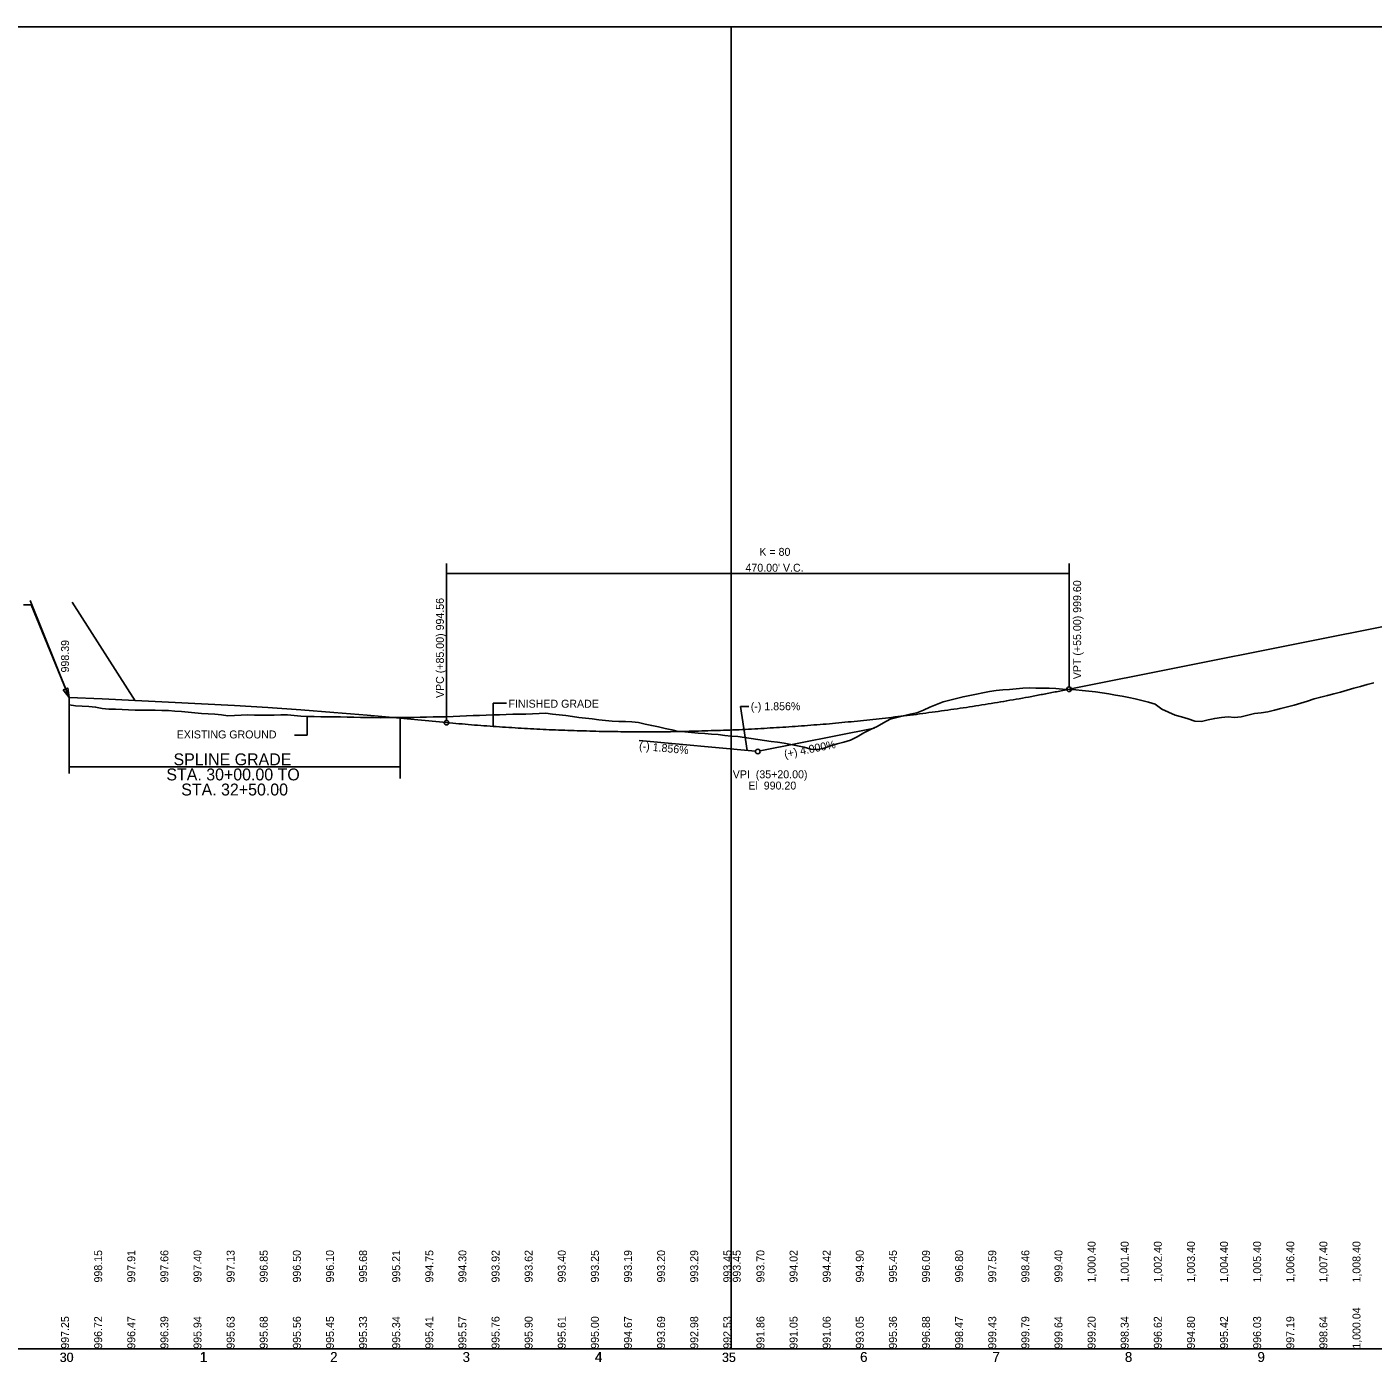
# Model space of a CAD drawing. Extents: x 1150 to 16975538, y 12057 to 12564120.
# Drawn here: x 16973506 to 16974522, y 12563110 to 12564118 of the extents above; entities that cross this region are included whole.
import ezdxf

# ---------------------------------------------------------------- set-up
doc = ezdxf.new("R2010")
doc.units = 0
for name, color, linetype in [('ANNOT_CONTOUR', 7, 'Continuous'), ('CLS_P_Shld_Gore', 7, 'Continuous'), ('Default', 7, 'Continuous'), ('RD_DDB_Profile_EX', 7, 'Continuous'), ('RD_DDB_StaTX', 7, 'Continuous'), ('RD_DDB_StripGrade', 7, 'Continuous'), ('RD_EX_Conc-ZZ', 7, 'Continuous'), ('RD_GPK_Profile_Cell', 7, 'Continuous'), ('RD_HC_CL_50', 7, 'Continuous'), ('RD_HC_TX_Sta20', 7, 'Continuous'), ('RD_PD_SuperShp1', 7, 'Continuous'), ('RD_Sketch1', 7, 'Continuous'), ('RD_Sketch7', 7, 'Continuous'), ('RD_TX_Utilities', 7, 'Continuous'), ('RD_XS_Misc_Line', 7, 'Continuous')]:
    doc.layers.add(name, color=color, linetype=linetype)

msp = doc.modelspace()

# ---------------------------------------------------------------- linework, layer by layer
at = {"layer": 'CLS_P_Shld_Gore'}
for p, q in [((16973868.1, 12563607.3), (16973858.1, 12563607.3)), ((16973858.1, 12563607.3), (16973858.1, 12563589.8))]:
    msp.add_line(p, q, dxfattribs=at)
at = {"layer": 'Default'}
for points in [[(16972537.8, 12563119.9), (16974037.8, 12563119.9), (16974037.8, 12564118.1), (16972537.8, 12564118.1)], [(16974037.8, 12563119.9), (16975537.8, 12563119.9), (16975537.8, 12564118.1), (16974037.8, 12564118.1)]]:
    msp.add_lwpolyline(points, close=True, dxfattribs=at)
at = {"layer": 'RD_DDB_Profile_EX'}
for points in [[(16974037.8, 12563582.6), (16974042.8, 12563582.2), (16974047.8, 12563581.6), (16974052.8, 12563580.7), (16974057.8, 12563579.9), (16974062.8, 12563579.2), (16974067.8, 12563578.5), (16974072.8, 12563577.9), (16974077.8, 12563577.2), (16974082.8, 12563576.2), (16974087.8, 12563575.2), (16974092.8, 12563574.1), (16974097.8, 12563572.8), (16974102.8, 12563572.4), (16974107.8, 12563573.4), (16974112.8, 12563575.2), (16974117.8, 12563576.6), (16974122.8, 12563577.9), (16974127.8, 12563579.5), (16974132.8, 12563581.9), (16974137.8, 12563585.1), (16974142.8, 12563587.5), (16974147.8, 12563589.9), (16974152.8, 12563592.6), (16974157.8, 12563595.3), (16974162.8, 12563596.7), (16974167.8, 12563597.9), (16974172.8, 12563599), (16974177.8, 12563600.1), (16974182.8, 12563602.1), (16974187.8, 12563604.3), (16974192.8, 12563606.5), (16974197.8, 12563608.4), (16974202.8, 12563609.7), (16974207.8, 12563611), (16974212.8, 12563612.3), (16974217.8, 12563613.1), (16974222.8, 12563614.1), (16974227.8, 12563615.2), (16974232.8, 12563616.3), (16974237.8, 12563617.1), (16974242.8, 12563617.5), (16974247.8, 12563617.8), (16974252.8, 12563618.2), (16974257.8, 12563618.7), (16974262.8, 12563618.9), (16974267.8, 12563618.8), (16974272.8, 12563618.7), (16974277.8, 12563618.8), (16974282.8, 12563618.5), (16974287.8, 12563618.1), (16974292.8, 12563617.7), (16974297.8, 12563617.4), (16974302.8, 12563617), (16974307.8, 12563616.6), (16974312.8, 12563615.9), (16974317.8, 12563615.2), (16974322.8, 12563614.4), (16974327.8, 12563613.5), (16974332.8, 12563612.6), (16974337.8, 12563611.6), (16974342.8, 12563610.6), (16974347.8, 12563609.4), (16974352.8, 12563608.1), (16974357.8, 12563606.7), (16974362.8, 12563603), (16974367.8, 12563600.6), (16974372.8, 12563598.4), (16974377.8, 12563597), (16974382.8, 12563595.5), (16974387.8, 12563593.9), (16974392.8, 12563593.6), (16974397.8, 12563594.8), (16974402.8, 12563595.9), (16974407.8, 12563596.7), (16974412.8, 12563597), (16974417.8, 12563596.7), (16974422.8, 12563597.2), (16974427.8, 12563598.4), (16974432.8, 12563599.5), (16974437.8, 12563600), (16974442.8, 12563600.9), (16974447.8, 12563602.2), (16974452.8, 12563603.5), (16974457.8, 12563604.7), (16974462.8, 12563605.9), (16974467.8, 12563607.3), (16974472.8, 12563609), (16974477.8, 12563610.6), (16974482.8, 12563612), (16974487.8, 12563613.1), (16974492.8, 12563614.5), (16974497.8, 12563615.8), (16974502.8, 12563617.2), (16974507.8, 12563618.7), (16974512.8, 12563620.1), (16974517.8, 12563621.4), (16974522.8, 12563622.7)], [(16973537.8, 12563606.1), (16973542.8, 12563605.5), (16973547.8, 12563605.2), (16973552.8, 12563605), (16973557.8, 12563604.5), (16973562.8, 12563603.5), (16973567.8, 12563603), (16973572.8, 12563602.8), (16973577.8, 12563602.7), (16973582.8, 12563602.5), (16973587.8, 12563602.2), (16973592.8, 12563602.2), (16973597.8, 12563602.2), (16973602.8, 12563602.2), (16973607.8, 12563602), (16973612.8, 12563601.8), (16973617.8, 12563601.4), (16973622.8, 12563601.2), (16973627.8, 12563600.7), (16973632.8, 12563600.2), (16973637.8, 12563599.6), (16973642.8, 12563599.3), (16973647.8, 12563599), (16973652.8, 12563598.5), (16973657.8, 12563597.9), (16973662.8, 12563598), (16973667.8, 12563598.3), (16973672.8, 12563598.5), (16973677.8, 12563598.4), (16973682.8, 12563598.3), (16973687.8, 12563598.3), (16973692.8, 12563598.3), (16973697.8, 12563598.7), (16973702.8, 12563598.7), (16973707.8, 12563598.2), (16973712.8, 12563597.7), (16973717.8, 12563597.4), (16973722.8, 12563597.3), (16973727.8, 12563597.2), (16973732.8, 12563597.1), (16973737.8, 12563597.2), (16973742.8, 12563597), (16973747.8, 12563596.9), (16973752.8, 12563596.8), (16973757.8, 12563596.7), (16973762.8, 12563596.6), (16973767.8, 12563596.5), (16973772.8, 12563596.4), (16973777.8, 12563596.5), (16973782.8, 12563596.6), (16973787.8, 12563596.6), (16973792.8, 12563596.7), (16973797.8, 12563596.7), (16973802.8, 12563596.8), (16973807.8, 12563596.9), (16973812.8, 12563597), (16973817.8, 12563597), (16973822.8, 12563597.1), (16973827.8, 12563597.3), (16973832.8, 12563597.6), (16973837.8, 12563597.8), (16973842.8, 12563598), (16973847.8, 12563598.2), (16973852.8, 12563598.4), (16973857.8, 12563598.5), (16973862.8, 12563598.7), (16973867.8, 12563598.9), (16973872.8, 12563599), (16973877.8, 12563599.1), (16973882.8, 12563599.2), (16973887.8, 12563599.4), (16973892.8, 12563599.6), (16973897.8, 12563599.8), (16973902.8, 12563599.1), (16973907.8, 12563598.5), (16973912.8, 12563598), (16973917.8, 12563597.3), (16973922.8, 12563596.7), (16973927.8, 12563596.1), (16973932.8, 12563595.5), (16973937.8, 12563594.9), (16973942.8, 12563594.4), (16973947.8, 12563593.9), (16973952.8, 12563593.6), (16973957.8, 12563593.5), (16973962.8, 12563593.3), (16973967.8, 12563592.8), (16973972.8, 12563591.6), (16973977.8, 12563590.5), (16973982.8, 12563589.5), (16973987.8, 12563588.4), (16973992.8, 12563587.2), (16973997.8, 12563586.1), (16974002.8, 12563585.7), (16974007.8, 12563585.2), (16974012.8, 12563584.8), (16974017.8, 12563584.4), (16974022.8, 12563584.1), (16974027.8, 12563583.7), (16974032.8, 12563583.1), (16974037.8, 12563582.6)]]:
    msp.add_lwpolyline(points, dxfattribs=at)
at = {"layer": 'RD_DDB_StripGrade'}
for p, q in [((16973537.8, 12563554.4), (16973537.8, 12563611.8)), ((16973787.8, 12563550.5), (16973787.8, 12563596)), ((16973537.8, 12563559.3), (16973787.8, 12563559.3))]:
    msp.add_line(p, q, dxfattribs=at)
at = {"layer": 'RD_EX_Conc-ZZ'}
for p, q in [((16974146, 12563588.6), (16974059.5, 12563571.3)), ((16973968.2, 12563579.2), (16974056, 12563571.1))]:
    msp.add_line(p, q, dxfattribs=at)
msp.add_circle((16974057.8, 12563570.9), 1.75, dxfattribs=at)
at = {"layer": 'RD_GPK_Profile_Cell'}
msp.add_line((16973037.6, 12563119.9), (16975355.1, 12563119.9), dxfattribs=at)
at = {"layer": 'RD_HC_TX_Sta20'}
for p, q in [((16973822.8, 12563712.9), (16973822.8, 12563594.5)), ((16974292.8, 12563712.9), (16974292.8, 12563619.7)), ((16973822.8, 12563705.4), (16974292.8, 12563705.4))]:
    msp.add_line(p, q, dxfattribs=at)
for centre in [(16974292.8, 12563617.9), (16973822.8, 12563592.7)]:
    msp.add_circle(centre, 1.75, dxfattribs=at)
at = {"layer": 'RD_PD_SuperShp1'}
for p, q in [((16974051, 12563604.9), (16974044.7, 12563604.9)), ((16974044.7, 12563604.9), (16974049.8, 12563571.7))]:
    msp.add_line(p, q, dxfattribs=at)
at = {"layer": 'RD_Sketch1'}
for p, q in [((16973537.8, 12563611.6), (16973508.5, 12563684.9)), ((16973587.8, 12563609.3), (16973540.2, 12563683.6))]:
    msp.add_line(p, q, dxfattribs=at)
at = {"layer": 'RD_Sketch7'}
for p, q in [((16973717.7, 12563583.2), (16973717.7, 12563597.4)), ((16973708, 12563583.2), (16973717.7, 12563583.2))]:
    msp.add_line(p, q, dxfattribs=at)
at = {"layer": 'RD_TX_Utilities'}
msp.add_lwpolyline([(16973503.5, 12563681.8), (16973509.3, 12563681.8), (16973537.8, 12563611.8)], dxfattribs=at)
msp.add_lwpolyline([(16973533.5, 12563617.4), (16973537.8, 12563611.8), (16973536.9, 12563618.8)], close=True, dxfattribs=at)
at = {"layer": 'RD_XS_Misc_Line'}
for p, q in [((16974292.8, 12563617.9), (16974627.8, 12563684.9)), ((16973537.8, 12563611.8), (16973562.8, 12563610.7)), ((16973562.8, 12563610.7), (16973587.8, 12563609.5)), ((16973587.8, 12563609.5), (16973612.8, 12563608.2)), ((16973612.8, 12563608.2), (16973637.8, 12563606.9)), ((16973637.8, 12563606.9), (16973662.8, 12563605.6)), ((16973662.8, 12563605.6), (16973687.8, 12563604.2)), ((16973687.8, 12563604.2), (16973712.8, 12563602.4)), ((16973712.8, 12563602.4), (16973737.8, 12563600.4)), ((16973737.8, 12563600.4), (16973762.8, 12563598.3)), ((16973762.8, 12563598.3), (16973787.8, 12563596)), ((16973787.8, 12563596), (16973822.8, 12563592.7))]:
    msp.add_line(p, q, dxfattribs=at)
msp.add_spline([(16973822.8, 12563592.7), (16973832.2, 12563591.9), (16973841.6, 12563591.1), (16973851, 12563590.4), (16973860.4, 12563589.7), (16973869.8, 12563589.1), (16973879.2, 12563588.5), (16973888.6, 12563588), (16973898, 12563587.5), (16973907.4, 12563587.1), (16973916.8, 12563586.8), (16973926.2, 12563586.5), (16973935.6, 12563586.2), (16973945, 12563586), (16973954.4, 12563585.9), (16973963.8, 12563585.8), (16973973.2, 12563585.8), (16973982.6, 12563585.9), (16973992, 12563585.9), (16974001.4, 12563586.1), (16974010.8, 12563586.3), (16974020.2, 12563586.6), (16974029.6, 12563586.9), (16974039, 12563587.2), (16974048.4, 12563587.6), (16974057.8, 12563588.1), (16974067.2, 12563588.7), (16974076.6, 12563589.2), (16974086, 12563589.9), (16974095.4, 12563590.6), (16974104.8, 12563591.3), (16974114.2, 12563592.1), (16974123.6, 12563593), (16974133, 12563593.9), (16974142.4, 12563594.9), (16974151.8, 12563595.9), (16974161.2, 12563597), (16974170.6, 12563598.1), (16974180, 12563599.3), (16974189.4, 12563600.6), (16974198.8, 12563601.9), (16974208.2, 12563603.2), (16974217.6, 12563604.6), (16974227, 12563606.1), (16974236.4, 12563607.6), (16974245.8, 12563609.2), (16974255.2, 12563610.8), (16974264.6, 12563612.5), (16974274, 12563614.3), (16974283.4, 12563616.1), (16974292.8, 12563617.9)], degree=3, dxfattribs=at)

# ---------------------------------------------------------------- texts
at = {"layer": 'ANNOT_CONTOUR'}
for s, p in [('997.25', (16973537.8, 12563119.9)), ('996.72', (16973562.8, 12563119.9)), ('996.47', (16973587.8, 12563119.9)), ('996.39', (16973612.8, 12563119.9)), ('995.94', (16973637.8, 12563119.9)), ('995.63', (16973662.8, 12563119.9)), ('995.68', (16973687.8, 12563119.9)), ('995.56', (16973712.8, 12563119.9)), ('995.45', (16973737.8, 12563119.9)), ('995.33', (16973762.8, 12563119.9)), ('995.34', (16973787.8, 12563119.9)), ('995.41', (16973812.8, 12563119.9)), ('995.57', (16973837.8, 12563119.9)), ('995.76', (16973862.8, 12563119.9)), ('995.90', (16973887.8, 12563119.9)), ('995.61', (16973912.8, 12563119.9)), ('995.00', (16973937.8, 12563119.9)), ('994.67', (16973962.8, 12563119.9)), ('993.69', (16973987.8, 12563119.9)), ('992.98', (16974012.8, 12563119.9)), ('992.53', (16974037.8, 12563119.9)), ('991.86', (16974062.8, 12563119.9)), ('991.05', (16974087.8, 12563119.9)), ('991.06', (16974112.8, 12563119.9)), ('993.05', (16974137.8, 12563119.9)), ('995.36', (16974162.8, 12563119.9)), ('996.88', (16974187.8, 12563119.9)), ('998.47', (16974212.8, 12563119.9)), ('999.43', (16974237.8, 12563119.9)), ('999.79', (16974262.8, 12563119.9)), ('999.64', (16974287.8, 12563119.9)), ('999.20', (16974312.8, 12563119.9)), ('998.34', (16974337.8, 12563119.9)), ('996.62', (16974362.8, 12563119.9)), ('994.80', (16974387.8, 12563119.9)), ('995.42', (16974412.8, 12563119.9)), ('996.03', (16974437.8, 12563119.9)), ('997.19', (16974462.8, 12563119.9)), ('998.64', (16974487.8, 12563119.9)), ('1,000.04', (16974512.8, 12563119.9))]:
    msp.add_text(s, height=6, rotation=90, dxfattribs=at).set_placement(p)
at = {"layer": 'CLS_P_Shld_Gore'}
msp.add_text('FINISHED GRADE', height=6, dxfattribs=at).set_placement((16973869.6, 12563604))
at = {"layer": 'RD_DDB_StaTX'}
for s, height, p in [('30', 7, (16973530.7, 12563109.9)), ('30', 7, (16973530.9, 12563109.9)), ('1', 7.5, (16973636.4, 12563109.9)), ('1', 7.5, (16973636.8, 12563109.9)), ('2', 7.5, (16973734.9, 12563109.9)), ('2', 7.5, (16973735, 12563109.9)), ('3', 7.5, (16973834.9, 12563109.9)), ('3', 7.5, (16973835, 12563109.9)), ('4', 7.5, (16973934.7, 12563109.9)), ('4', 7.5, (16973935, 12563109.9)), ('35', 7, (16974030.7, 12563109.9)), ('35', 7, (16974030.9, 12563109.9)), ('6', 7.5, (16974135, 12563109.9)), ('6', 7.5, (16974135.1, 12563109.9)), ('7', 7.5, (16974234.9, 12563109.9)), ('7', 7.5, (16974235, 12563109.9)), ('8', 7.5, (16974334.9, 12563109.9)), ('8', 7.5, (16974335, 12563109.9)), ('9', 7.5, (16974435, 12563109.9)), ('9', 7.5, (16974435.1, 12563109.9))]:
    msp.add_text(s, height=height, dxfattribs=at).set_placement(p)
at = {"layer": 'RD_DDB_StripGrade'}
for s, p in [('SPLINE GRADE', (16973616.7, 12563560.5)), ('STA. 30+00.00 TO', (16973611.3, 12563549.1)), ('STA. 32+50.00', (16973622.5, 12563537.7))]:
    msp.add_text(s, height=9, dxfattribs=at).set_placement(p)
at = {"layer": 'RD_EX_Conc-ZZ'}
msp.add_text('998.39', height=6, rotation=90, dxfattribs=at).set_placement((16973537.8, 12563630.6))
for s, p in [('VPI  (35+20.00)', (16974038.9, 12563550.7)), ('El  990.20', (16974050.7, 12563542.2))]:
    msp.add_text(s, height=6, dxfattribs=at).set_placement(p)
at = {"layer": 'RD_HC_CL_50'}
for s, p in [('1,000.40', (16974312.8, 12563169.9)), ('1,001.40', (16974337.8, 12563169.9)), ('1,002.40', (16974362.8, 12563169.9)), ('1,003.40', (16974387.8, 12563169.9)), ('1,004.40', (16974412.8, 12563169.9)), ('1,005.40', (16974437.8, 12563169.9)), ('1,006.40', (16974462.8, 12563169.9)), ('1,007.40', (16974487.8, 12563169.9)), ('1,008.40', (16974512.8, 12563169.9)), ('998.15', (16973562.8, 12563169.9)), ('997.91', (16973587.8, 12563169.9)), ('997.66', (16973612.8, 12563169.9)), ('997.40', (16973637.8, 12563169.9)), ('997.13', (16973662.8, 12563169.9)), ('996.85', (16973687.8, 12563169.9)), ('996.50', (16973712.8, 12563169.9)), ('996.10', (16973737.8, 12563169.9)), ('995.68', (16973762.8, 12563169.9)), ('995.21', (16973787.8, 12563169.9)), ('994.75', (16973812.8, 12563169.9)), ('994.30', (16973837.8, 12563169.9)), ('993.92', (16973862.8, 12563169.9)), ('993.62', (16973887.8, 12563169.9)), ('993.40', (16973912.8, 12563169.9)), ('993.25', (16973937.8, 12563169.9)), ('993.19', (16973962.8, 12563169.9)), ('993.20', (16973987.8, 12563169.9)), ('993.29', (16974012.8, 12563169.9)), ('993.45', (16974037.8, 12563169.9)), ('993.45', (16974044.9, 12563169.9)), ('993.70', (16974062.8, 12563169.9)), ('994.02', (16974087.8, 12563169.9)), ('994.42', (16974112.8, 12563169.9)), ('994.90', (16974137.8, 12563169.9)), ('995.45', (16974162.8, 12563169.9)), ('996.09', (16974187.8, 12563169.9)), ('996.80', (16974212.8, 12563169.9)), ('997.59', (16974237.8, 12563169.9)), ('998.46', (16974262.8, 12563169.9)), ('999.40', (16974287.8, 12563169.9))]:
    msp.add_text(s, height=6, rotation=90, dxfattribs=at).set_placement(p)
at = {"layer": 'RD_HC_TX_Sta20'}
for s, p in [('K = 80', (16974059, 12563718.7)), ("470.00' V.C.", (16974048.5, 12563706.7))]:
    msp.add_text(s, height=6, dxfattribs=at).set_placement(p)
for s, p in [('VPT (+55.00) 999.60', (16974301.9, 12563625.5)), ('VPC (+85.00) 994.56', (16973820.8, 12563611.3))]:
    msp.add_text(s, height=6, rotation=90, dxfattribs=at).set_placement(p)
at = {"layer": 'RD_PD_SuperShp1'}
msp.add_text('(-) 1.856%', height=6, dxfattribs=at).set_placement((16974052.5, 12563602.1))
for s, rotation, p in [('(-) 1.856%', 354.6978, (16973968, 12563572.3)), ('(+) 4.000%', 11.3099, (16974078.3, 12563565.9))]:
    msp.add_text(s, height=6, rotation=rotation, dxfattribs=at).set_placement(p)
at = {"layer": 'RD_Sketch7'}
msp.add_text('EXISTING GROUND', height=6, dxfattribs=at).set_placement((16973619.1, 12563580.8))

doc.saveas('drawing.dxf')
